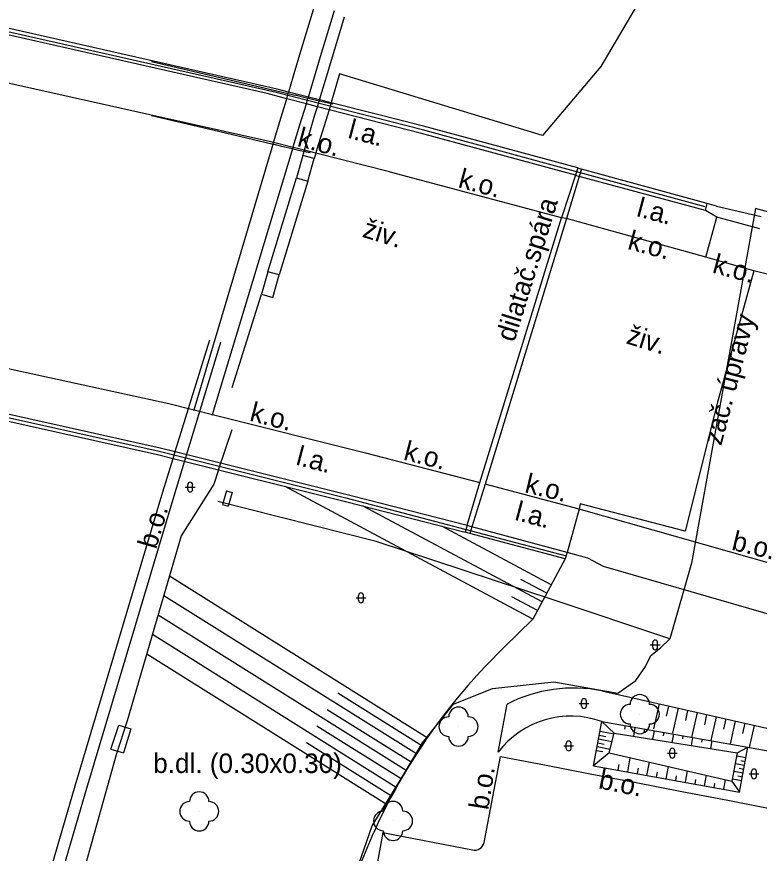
# Model space of a CAD drawing. Extents: x -601602 to -600882, y -1162594 to -1161950.
# Drawn here: x -601569.41 to -601531.37, y -1162301.67 to -1162258.81 of the extents above; entities that cross this region are included whole.
import ezdxf

# ---------------------------------------------------------------- set-up
doc = ezdxf.new("R2010")
doc.units = 0
for name, color, linetype in [('VRSTVA 1', 7, 'Continuous'), ('Vrstva 13', 7, 'Continuous'), ('Vrstva 14', 7, 'Continuous'), ('Vrstva 16', 7, 'Continuous'), ('Vrstva 8', 7, 'Continuous')]:
    doc.layers.add(name, color=color, linetype=linetype)

msp = doc.modelspace()

# ---------------------------------------------------------------- linework, layer by layer
at = {"layer": 'VRSTVA 1'}
msp.add_line((-601535.95, -1162290.68), (-601536.43, -1162291.15), dxfattribs=at)
for points in [[(-601331.31, -1162306.58), (-601332.3, -1162306.37), (-601334.05, -1162306.03), (-601365.21, -1162299.85), (-601405.05, -1162291.66), (-601414.46, -1162290.57), (-601424.01, -1162291.3), (-601452.18, -1162285.72), (-601481.36, -1162280.32), (-601487.9, -1162279.02), (-601506.8, -1162275.08), (-601511.71, -1162274.13), (-601531.56, -1162268.63), (-601534.84, -1162286.8), (-601535.95, -1162290.68)], [(-601535.95, -1162290.68), (-601541.93, -1162288.69), (-601550.99, -1162285.7), (-601559.11, -1162283.64)], [(-601552.28, -1162303.36), (-601551.21, -1162300.27), (-601549.56, -1162297.6), (-601548.62, -1162296.01), (-601547.03, -1162294.03), (-601545.04, -1162293.22), (-601541.9, -1162292.89), (-601538.62, -1162293.46), (-601537.69, -1162292.81), (-601537.2, -1162292.1), (-601536.92, -1162291.53), (-601536.43, -1162291.15)]]:
    msp.add_lwpolyline(points, dxfattribs=at)
at = {"layer": 'Vrstva 13'}
for p, q in [((-601554.74, -1162260.18), (-601553.14, -1162254.87)), ((-601553.84, -1162260.84), (-601553.13, -1162258.49)), ((-601556.07, -1162262.52), (-601572.196, -1162258.872)), ((-601553.37, -1162261.32), (-601552.62, -1162258.81)), ((-601556.58, -1162262.75), (-601572.268, -1162259.201)), ((-601555.11, -1162261.42), (-601554.74, -1162260.18)), ((-601554.47, -1162262.93), (-601553.84, -1162260.84)), ((-601562.5, -1162261.11), (-601555.5, -1162262.75)), ((-601555.47, -1162262.65), (-601555.11, -1162261.42)), ((-601553.9, -1162263.07), (-601553.37, -1162261.32)), ((-601556.85, -1162265.11), (-601572.784, -1162261.553)), ((-601552.868, -1162261.734), (-601553.308, -1162263.2)), ((-601542.478, -1162264.896), (-601552.868, -1162261.734)), ((-601555.58, -1162263.01), (-601556.58, -1162262.75)), ((-601555.48, -1162262.67), (-601556.07, -1162262.52)), ((-601555.58, -1162263.01), (-601555.5, -1162262.75)), ((-601555.5, -1162262.75), (-601555.48, -1162262.67)), ((-601555.5, -1162262.75), (-601555.17, -1162262.833)), ((-601555.48, -1162262.67), (-601555.47, -1162262.65)), ((-601554.47, -1162262.93), (-601555.48, -1162262.67)), ((-601555.86, -1162263.95), (-601555.58, -1162263.01)), ((-601554.57, -1162263.27), (-601555.58, -1162263.01)), ((-601554.49, -1162262.99), (-601555.17, -1162262.83)), ((-601554.57, -1162263.27), (-601554.55, -1162263.2)), ((-601554.55, -1162263.2), (-601554.49, -1162262.99)), ((-601554.49, -1162262.99), (-601554.47, -1162262.93)), ((-601554.26, -1162263.05), (-601554.49, -1162262.99)), ((-601553.9, -1162263.07), (-601554.47, -1162262.93)), ((-601553.92, -1162263.13), (-601554.26, -1162263.05)), ((-601554, -1162263.42), (-601553.92, -1162263.13)), ((-601553.92, -1162263.13), (-601553.9, -1162263.07)), ((-601553.35, -1162263.26), (-601553.92, -1162263.13)), ((-601553.31, -1162263.22), (-601553.9, -1162263.07)), ((-601553.308, -1162263.2), (-601553.31, -1162263.22)), ((-601554.9, -1162264.34), (-601554.57, -1162263.27)), ((-601554, -1162263.42), (-601554.57, -1162263.27)), ((-601554.13, -1162263.84), (-601554, -1162263.42)), ((-601553.41, -1162263.57), (-601554.03, -1162265.598)), ((-601553.41, -1162263.57), (-601554, -1162263.42)), ((-601553.32, -1162263.27), (-601553.41, -1162263.57)), ((-601548.67, -1162264.79), (-601553.41, -1162263.57)), ((-601553.32, -1162263.27), (-601553.35, -1162263.26)), ((-601553.31, -1162263.22), (-601553.32, -1162263.27)), ((-601553.21, -1162263.29), (-601553.32, -1162263.27)), ((-601550.93, -1162263.82), (-601553.31, -1162263.22)), ((-601562.5, -1162263.87), (-601559.37, -1162264.61)), ((-601556.25, -1162265.25), (-601555.86, -1162263.95)), ((-601554.4, -1162264.73), (-601554.13, -1162263.84)), ((-601549.92, -1162264.08), (-601550.93, -1162263.82)), ((-601555.24, -1162265.48), (-601554.9, -1162264.34)), ((-601548.57, -1162264.42), (-601549.92, -1162264.08)), ((-601540.67, -1162266.55), (-601548.57, -1162264.42)), ((-601559.37, -1162264.61), (-601556.27, -1162265.33)), ((-601554.67, -1162265.63), (-601554.4, -1162264.73)), ((-601540.792, -1162266.92), (-601548.67, -1162264.79)), ((-601558.29, -1162272.12), (-601556.27, -1162265.33)), ((-601556.25, -1162265.26), (-601556.85, -1162265.11)), ((-601556.27, -1162265.33), (-601556.25, -1162265.26)), ((-601556.27, -1162265.33), (-601556.24, -1162265.34)), ((-601555.25, -1162265.51), (-601556.25, -1162265.26)), ((-601556.24, -1162265.34), (-601555.77, -1162265.45)), ((-601557.32, -1162272.36), (-601555.25, -1162265.51)), ((-601555.77, -1162265.45), (-601555.28, -1162265.56)), ((-601554.67, -1162265.65), (-601555.25, -1162265.51)), ((-601555.25, -1162265.57), (-601554.97, -1162265.64)), ((-601554.97, -1162265.64), (-601554.7, -1162265.7)), ((-601554.71, -1162265.78), (-601554.69, -1162265.7)), ((-601554.7, -1162265.7), (-601554.69, -1162265.7)), ((-601554.69, -1162265.7), (-601554.67, -1162265.65)), ((-601554.69, -1162265.7), (-601554.64, -1162265.71)), ((-601554.09, -1162265.8), (-601554.67, -1162265.65)), ((-601554.64, -1162265.71), (-601554.58, -1162265.73)), ((-601554.58, -1162265.73), (-601554.38, -1162265.77)), ((-601554.086, -1162265.778), (-601554.09, -1162265.8)), ((-601554.03, -1162265.598), (-601554.086, -1162265.778)), ((-601554.75, -1162265.92), (-601555.08, -1162267.07)), ((-601554.75, -1162265.92), (-601554.71, -1162265.78)), ((-601554.18, -1162266.08), (-601554.75, -1162265.92)), ((-601554.5, -1162267.24), (-601554.18, -1162266.08)), ((-601554.09, -1162265.8), (-601554.176, -1162266.082)), ((-601550.31, -1162266.76), (-601554.09, -1162265.8)), ((-601540.67, -1162266.55), (-601540.79, -1162266.92)), ((-601540.67, -1162266.55), (-601540.48, -1162266.61)), ((-601540.48, -1162266.61), (-601540.6, -1162266.99)), ((-601534.04, -1162268.37), (-601540.48, -1162266.61)), ((-601550.14, -1162266.8), (-601550.31, -1162266.76)), ((-601541.51, -1162269.11), (-601550.14, -1162266.8)), ((-601540.79, -1162266.92), (-601541.51, -1162269.11)), ((-601540.6, -1162266.99), (-601541.25, -1162269.15)), ((-601540.792, -1162266.92), (-601540.79, -1162266.92)), ((-601540.79, -1162266.92), (-601540.6, -1162266.99)), ((-601534.13, -1162268.73), (-601540.6, -1162266.99)), ((-601540.6, -1162266.99), (-601540.595, -1162266.99)), ((-601554.5, -1162267.24), (-601555.96, -1162272.03)), ((-601555.81, -1162269.47), (-601555.08, -1162267.07)), ((-601555.08, -1162267.07), (-601554.5, -1162267.24)), ((-601534.13, -1162268.73), (-601534.04, -1162268.37)), ((-601533.55, -1162269.07), (-601534.13, -1162268.73)), ((-601545.68, -1162282.68), (-601541.51, -1162269.11)), ((-601541.25, -1162269.15), (-601545.42, -1162282.75)), ((-601541.25, -1162269.15), (-601541.51, -1162269.11)), ((-601534.113, -1162271.135), (-601541.25, -1162269.15)), ((-601534.113, -1162271.135), (-601533.55, -1162269.07)), ((-601531.35, -1162269.67), (-601533.55, -1162269.07)), ((-601556.54, -1162271.87), (-601555.81, -1162269.47)), ((-601531.65, -1162271.82), (-601534.113, -1162271.135)), ((-601560.32, -1162278.95), (-601558.29, -1162272.12)), ((-601556.54, -1162271.87), (-601556.87, -1162273.02)), ((-601555.96, -1162272.03), (-601556.54, -1162271.87)), ((-601556.29, -1162273.19), (-601555.96, -1162272.03)), ((-601531.65, -1162271.82), (-601533.53, -1162278.62)), ((-601527.21, -1162272.99), (-601531.65, -1162271.82)), ((-601559.38, -1162279.19), (-601557.32, -1162272.36)), ((-601557.63, -1162275.42), (-601556.87, -1162273.02)), ((-601556.87, -1162273.02), (-601556.29, -1162273.19)), ((-601560.61, -1162278.88), (-601559.523, -1162275.355)), ((-601558.38, -1162277.81), (-601557.63, -1162275.42)), ((-601572.47, -1162276.25), (-601561.62, -1162278.63)), ((-601573.14, -1162278.43), (-601562.06, -1162280.9)), ((-601561.62, -1162278.63), (-601560.61, -1162278.88)), ((-601533.53, -1162278.62), (-601535.17, -1162285.16)), ((-601573.24, -1162278.78), (-601562.19, -1162281.24)), ((-601561.29, -1162281.09), (-601560.61, -1162278.88)), ((-601560.61, -1162278.88), (-601560.32, -1162278.95)), ((-601560.33, -1162278.99), (-601560.32, -1162278.95)), ((-601560.32, -1162278.95), (-601559.38, -1162279.19)), ((-601559.39, -1162279.22), (-601559.38, -1162279.19)), ((-601559.38, -1162279.19), (-601551.55, -1162281.16)), ((-601562.06, -1162280.9), (-601561.29, -1162281.09)), ((-601561.39, -1162281.44), (-601561.29, -1162281.09)), ((-601561.29, -1162281.09), (-601552.21, -1162283.36)), ((-601551.55, -1162281.16), (-601545.68, -1162282.68)), ((-601562.19, -1162281.24), (-601561.394, -1162281.439)), ((-601561.92, -1162283.15), (-601561.39, -1162281.44)), ((-601561.39, -1162281.44), (-601561.394, -1162281.439)), ((-601561.39, -1162281.44), (-601552.56, -1162283.65)), ((-601546.34, -1162284.86), (-601545.68, -1162282.68)), ((-601545.42, -1162282.75), (-601546.1, -1162284.94)), ((-601540.6, -1162284.04), (-601545.42, -1162282.75)), ((-601566.41, -1162298.21), (-601561.92, -1162283.15)), ((-601552.56, -1162283.65), (-601546.43, -1162285.21)), ((-601552.21, -1162283.36), (-601546.34, -1162284.86)), ((-601540.54, -1162283.76), (-601540.6, -1162284.04)), ((-601535.17, -1162285.16), (-601540.54, -1162283.76)), ((-601540.6, -1162284.04), (-601541.21, -1162286.26)), ((-601524.49, -1162288.62), (-601540.6, -1162284.04)), ((-601546.34, -1162284.86), (-601546.43, -1162285.21)), ((-601546.34, -1162284.86), (-601546.1, -1162284.94)), ((-601546.1, -1162284.94), (-601546.2, -1162285.28)), ((-601541.21, -1162286.26), (-601546.1, -1162284.94)), ((-601546.2, -1162285.28), (-601546.43, -1162285.21)), ((-601541.32, -1162286.59), (-601546.2, -1162285.28)), ((-601541.21, -1162286.26), (-601541.32, -1162286.59)), ((-601540.16, -1162286.54), (-601541.21, -1162286.26)), ((-601539.35, -1162286.98), (-601540.16, -1162286.54)), ((-601524.63, -1162291.24), (-601539.35, -1162286.98)), ((-601564.58, -1162296.34), (-601564.18, -1162295.1)), ((-601564.18, -1162295.1), (-601563.57, -1162295.3)), ((-601563.57, -1162295.3), (-601563.94, -1162296.53)), ((-601564.58, -1162296.34), (-601563.94, -1162296.53)), ((-601545.47, -1162301.11), (-601544.62, -1162296.71)), ((-601544.62, -1162296.71), (-601542.38, -1162297.14)), ((-601542.38, -1162297.14), (-601540.03, -1162297.59)), ((-601540.03, -1162297.59), (-601537.68, -1162298.04)), ((-601571.05, -1162314.04), (-601566.41, -1162298.21)), ((-601537.68, -1162298.04), (-601535.34, -1162298.5)), ((-601535.34, -1162298.5), (-601532.99, -1162298.95)), ((-601532.99, -1162298.95), (-601530.66, -1162299.41)), ((-601550.65, -1162300.61), (-601551.19, -1162303.49)), ((-601550.65, -1162300.61), (-601546.07, -1162301.5))]:
    msp.add_line(p, q, dxfattribs=at)
msp.add_arc((-601545.958, -1162301.015), 0.497, 257.0099, 349.0378, dxfattribs=at)
at = {"layer": 'Vrstva 14'}
for p, q in [((-601537.02, -1162257.17), (-601539.48, -1162261.36)), ((-601539.48, -1162261.36), (-601542.478, -1162264.896)), ((-601533.56, -1162268.51), (-601534.04, -1162268.37)), ((-601533.56, -1162268.51), (-601531.28, -1162269.04)), ((-601559.065, -1162282.022), (-601558.38, -1162279.96)), ((-601559.065, -1162282.022), (-601559.31, -1162282.76)), ((-601559.31, -1162282.76), (-601560.98, -1162285.41)), ((-601560.772, -1162282.908), (-601560.272, -1162282.908)), ((-601560.647, -1162283.033), (-601560.647, -1162282.783)), ((-601560.397, -1162283.033), (-601560.397, -1162282.783)), ((-601542.97, -1162289.67), (-601555.658, -1162282.875)), ((-601542.498, -1162288.789), (-601551.671, -1162283.876)), ((-601542.026, -1162287.907), (-601547.631, -1162284.904)), ((-601560.98, -1162285.41), (-601563.75, -1162294.88)), ((-601541.32, -1162286.59), (-601542.97, -1162289.67)), ((-601548.381, -1162295.748), (-601561.584, -1162287.476)), ((-601542.262, -1162288.348), (-601543.578, -1162287.643)), ((-601548.938, -1162296.58), (-601561.876, -1162288.473)), ((-601551.902, -1162288.707), (-601551.902, -1162288.457)), ((-601551.652, -1162288.707), (-601551.652, -1162288.457)), ((-601552.027, -1162288.582), (-601551.527, -1162288.582)), ((-601542.734, -1162289.229), (-601544.05, -1162288.524)), ((-601549.466, -1162297.429), (-601562.168, -1162289.47)), ((-601542.97, -1162289.67), (-601544.45, -1162291.13)), ((-601549.967, -1162298.295), (-601562.459, -1162290.466)), ((-601536.953, -1162290.993), (-601536.453, -1162290.993)), ((-601536.828, -1162291.118), (-601536.828, -1162290.868)), ((-601536.578, -1162291.118), (-601536.578, -1162290.868)), ((-601550.441, -1162299.179), (-601562.751, -1162291.464)), ((-601548.663, -1162296.162), (-601552.968, -1162293.464)), ((-601539.43, -1162293.35), (-601530.83, -1162295.3)), ((-601544.75, -1162296.49), (-601544.29, -1162294.03)), ((-601540.601, -1162293.997), (-601540.101, -1162293.997)), ((-601540.476, -1162294.122), (-601540.476, -1162293.872)), ((-601540.226, -1162294.122), (-601540.226, -1162293.872)), ((-601536.505, -1162294.013), (-601536.796, -1162295.294)), ((-601549.205, -1162297.002), (-601553.499, -1162294.311)), ((-601536.018, -1162294.124), (-601536.134, -1162294.637)), ((-601535.53, -1162294.234), (-601535.821, -1162295.517)), ((-601535.042, -1162294.345), (-601535.159, -1162294.858)), ((-601534.555, -1162294.455), (-601534.846, -1162295.74)), ((-601563.75, -1162294.88), (-601564.31, -1162296.62)), ((-601539.87, -1162297.18), (-601539.43, -1162294.92)), ((-601539.43, -1162294.92), (-601531.95, -1162296.23)), ((-601539.43, -1162294.92), (-601538.81, -1162295.51)), ((-601534.067, -1162294.566), (-601534.184, -1162295.08)), ((-601533.579, -1162294.677), (-601533.856, -1162295.896)), ((-601533.092, -1162294.787), (-601533.209, -1162295.302)), ((-601532.604, -1162294.898), (-601532.869, -1162296.069)), ((-601549.72, -1162297.86), (-601554.03, -1162295.159)), ((-601538.236, -1162295.129), (-601538.268, -1162295.313)), ((-601537.743, -1162295.215), (-601537.822, -1162295.668)), ((-601537.251, -1162295.302), (-601537.282, -1162295.48)), ((-601532.117, -1162295.008), (-601532.234, -1162295.524)), ((-601531.629, -1162295.119), (-601531.883, -1162296.243)), ((-601539.237, -1162295.694), (-601539.568, -1162295.629)), ((-601538.825, -1162295.571), (-601539.53, -1162295.433)), ((-601539.06, -1162296.53), (-601538.81, -1162295.51)), ((-601538.81, -1162295.51), (-601532.5, -1162296.52)), ((-601536.758, -1162295.388), (-601536.835, -1162295.826)), ((-601536.266, -1162295.474), (-601536.296, -1162295.647)), ((-601535.773, -1162295.56), (-601535.847, -1162295.984)), ((-601535.281, -1162295.647), (-601535.31, -1162295.813)), ((-601534.788, -1162295.733), (-601534.86, -1162296.142)), ((-601550.207, -1162298.734), (-601554.561, -1162296.007)), ((-601541.386, -1162296.169), (-601540.886, -1162296.169)), ((-601541.261, -1162296.294), (-601541.261, -1162296.044)), ((-601541.011, -1162296.294), (-601541.011, -1162296.044)), ((-601539.314, -1162296.087), (-601539.645, -1162296.022)), ((-601538.92, -1162295.96), (-601539.607, -1162295.826)), ((-601534.296, -1162295.819), (-601534.324, -1162295.98)), ((-601533.803, -1162295.905), (-601533.872, -1162296.3)), ((-601564.31, -1162296.62), (-601568.86, -1162312.86)), ((-601539.06, -1162296.53), (-601539.87, -1162297.18)), ((-601539.391, -1162296.479), (-601539.722, -1162296.414)), ((-601539.015, -1162296.348), (-601539.683, -1162296.218)), ((-601539.06, -1162296.53), (-601532.78, -1162297.97)), ((-601536.075, -1162296.539), (-601535.575, -1162296.539)), ((-601535.95, -1162296.664), (-601535.95, -1162296.414)), ((-601535.7, -1162296.664), (-601535.7, -1162296.414)), ((-601532.5, -1162296.52), (-601532.78, -1162297.97)), ((-601532.5, -1162296.52), (-601531.95, -1162296.23)), ((-601532.38, -1162298.53), (-601531.95, -1162296.23)), ((-601531.95, -1162296.23), (-601522.55, -1162298.02)), ((-601538.108, -1162297.498), (-601537.978, -1162296.778)), ((-601537.124, -1162297.675), (-601537.003, -1162297.002)), ((-601532.53, -1162296.678), (-601532.05, -1162296.767)), ((-601532.324, -1162296.92), (-601532.087, -1162296.964)), ((-601539.87, -1162297.18), (-601532.38, -1162298.53)), ((-601538.6, -1162297.409), (-601538.546, -1162297.112)), ((-601537.616, -1162297.586), (-601537.566, -1162297.308)), ((-601536.139, -1162297.852), (-601536.026, -1162297.226)), ((-601535.155, -1162298.03), (-601535.05, -1162297.449)), ((-601532.682, -1162297.464), (-601532.196, -1162297.554)), ((-601532.606, -1162297.07), (-601532.123, -1162297.16)), ((-601532.397, -1162297.313), (-601532.16, -1162297.357)), ((-601531.77, -1162297.727), (-601531.77, -1162297.477)), ((-601531.52, -1162297.727), (-601531.52, -1162297.477)), ((-601536.631, -1162297.764), (-601536.584, -1162297.504)), ((-601535.647, -1162297.941), (-601535.604, -1162297.7)), ((-601534.663, -1162298.118), (-601534.623, -1162297.896)), ((-601534.171, -1162298.207), (-601534.075, -1162297.673)), ((-601533.187, -1162298.385), (-601533.099, -1162297.897)), ((-601532.758, -1162297.856), (-601532.269, -1162297.947)), ((-601532.47, -1162297.707), (-601532.233, -1162297.751)), ((-601531.895, -1162297.602), (-601531.395, -1162297.602)), ((-601533.679, -1162298.296), (-601533.642, -1162298.092)), ((-601532.78, -1162297.97), (-601532.38, -1162298.53))]:
    msp.add_line(p, q, dxfattribs=at)
for centre in [(-601537.49, -1162294.54), (-601546.78, -1162295.18), (-601560.06, -1162299.52), (-601550.13, -1162300.01)]:
    msp.add_circle(centre, 0.0005, dxfattribs=at)
for centre, radius, start, end in [((-601560.521, -1162282.783), 0.125, 0, 180), ((-601560.521, -1162283.033), 0.125, 180, 360), ((-601551.776, -1162288.457), 0.125, 0, 180), ((-601551.776, -1162288.707), 0.125, 180, 360), ((-601536.702, -1162290.868), 0.125, 0, 180), ((-601523.195, -1162313.204), 30.643, 133.9172, 160.2723), ((-601536.702, -1162291.118), 0.125, 180, 360), ((-601540.901, -1162300.546), 7.345, 78.4488, 117.4811), ((-601537.49, -1162294.04), 0.5, 0, 180), ((-601540.351, -1162293.872), 0.125, 0, 180), ((-601537.99, -1162294.54), 0.5, 90, 270), ((-601536.99, -1162294.54), 0.5, 270, 90), ((-601546.78, -1162294.68), 0.5, 0, 180), ((-601540.351, -1162294.122), 0.125, 180, 360), ((-601547.28, -1162295.18), 0.5, 90, 270), ((-601546.28, -1162295.18), 0.5, 270, 90), ((-601541.019, -1162299.335), 4.692, 70.2061, 142.6779), ((-601537.49, -1162295.04), 0.5, 180, 360), ((-601546.78, -1162295.68), 0.5, 180, 360), ((-601541.136, -1162296.044), 0.125, 0, 180), ((-601541.136, -1162296.294), 0.125, 180, 360), ((-601535.825, -1162296.414), 0.125, 0, 180), ((-601535.825, -1162296.664), 0.125, 180, 360), ((-601531.645, -1162297.477), 0.125, 0, 180), ((-601531.645, -1162297.727), 0.125, 180, 360), ((-601560.06, -1162299.02), 0.5, 0, 180), ((-601560.56, -1162299.52), 0.5, 90, 270), ((-601559.56, -1162299.52), 0.5, 270, 90), ((-601550.13, -1162299.51), 0.5, 0, 180), ((-601550.63, -1162300.01), 0.5, 90, 270), ((-601549.63, -1162300.01), 0.5, 270, 90), ((-601560.06, -1162300.02), 0.5, 180, 360), ((-601550.13, -1162300.51), 0.5, 180, 360)]:
    msp.add_arc(centre, radius, start, end, dxfattribs=at)
at = {"layer": 'Vrstva 8'}
for p, q in [((-601556.12, -1162262.69), (-601572.234, -1162259.045)), ((-601548.62, -1162264.6), (-601556.12, -1162262.69)), ((-601534.14, -1162268.55), (-601548.62, -1162264.6)), ((-601558.976, -1162275.496), (-601561.36, -1162283.37)), ((-601576.37, -1162277.894), (-601562.12, -1162281.06)), ((-601562.12, -1162281.06), (-601552.55, -1162283.45)), ((-601558.66, -1162283.09), (-601558.86, -1162283.8)), ((-601558.66, -1162283.09), (-601558.37, -1162283.18)), ((-601558.37, -1162283.18), (-601558.57, -1162283.89)), ((-601561.36, -1162283.37), (-601565.84, -1162298.35)), ((-601552.55, -1162283.45), (-601541.27, -1162286.43)), ((-601558.86, -1162283.8), (-601558.57, -1162283.89)), ((-601565.84, -1162298.35), (-601570.47, -1162314.11))]:
    msp.add_line(p, q, dxfattribs=at)

# ---------------------------------------------------------------- texts
at = {"layer": 'Vrstva 16'}
for s, rotation, p in [('l.a.', 345.1615, (-601552.49, -1162265.004)), ('k.o.', 344.9685, (-601555.085, -1162265.423)), ('k.o.', 344.9685, (-601546.842, -1162267.532)), ('dilatač.spára', 72.8001, (-601543.921, -1162275.514)), ('l.a.', 345.1615, (-601537.706, -1162269.016)), ('živ.', 342.9797, (-601551.752, -1162270.077)), ('k.o.', 344.9685, (-601538.164, -1162270.699)), ('k.o.', 344.9685, (-601533.82, -1162271.91)), ('zač. úpravy', 75.3241, (-601533.32, -1162280.819)), ('živ.', 342.9797, (-601538.236, -1162275.535)), ('k.o.', 345.4825, (-601557.522, -1162279.495)), ('l.a.', 345.1615, (-601555.151, -1162281.744)), ('k.o.', 345.4825, (-601549.643, -1162281.489)), ('k.o.', 346.2919, (-601543.432, -1162283.164)), ('l.a.', 345.1615, (-601543.941, -1162284.573)), ('b.o.', 73.4799, (-601562.271, -1162286.128)), ('b.o.', 346.2919, (-601532.835, -1162286.106)), ('b.o.', 80.8929, (-601545.26, -1162299.482)), ('b.o.', 348.6008, (-601539.649, -1162298.332))]:
    msp.add_text(s, height=1, rotation=rotation, dxfattribs=at).set_placement(p)
msp.add_text('b.dl. (0.30x0.30)', height=1, dxfattribs=at).set_placement((-601562.417, -1162297.555))

doc.saveas('drawing.dxf')
